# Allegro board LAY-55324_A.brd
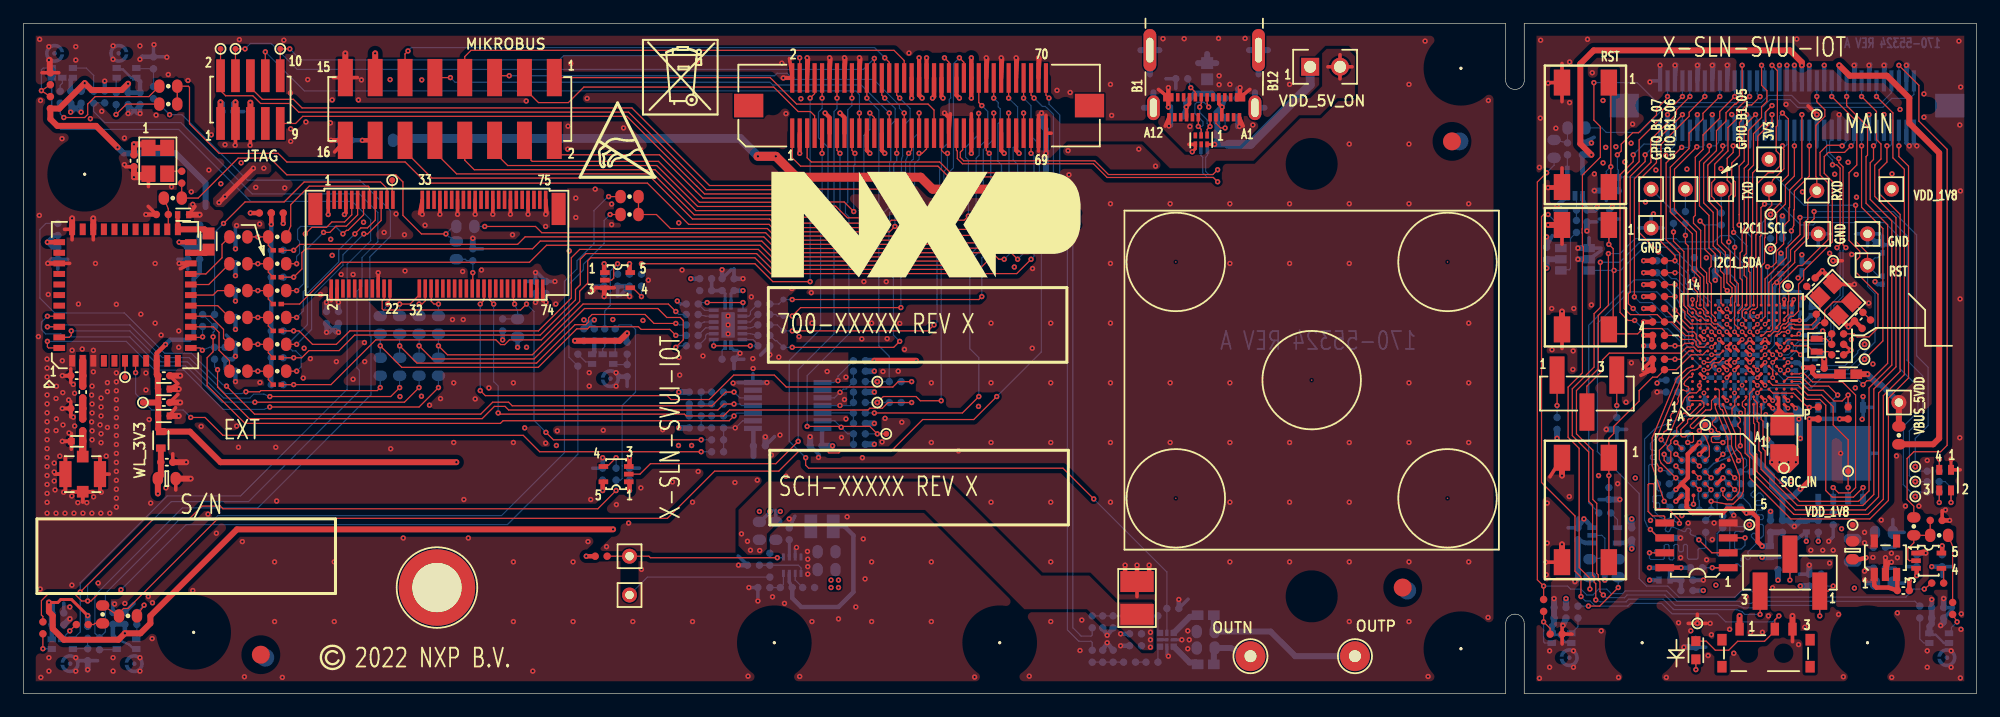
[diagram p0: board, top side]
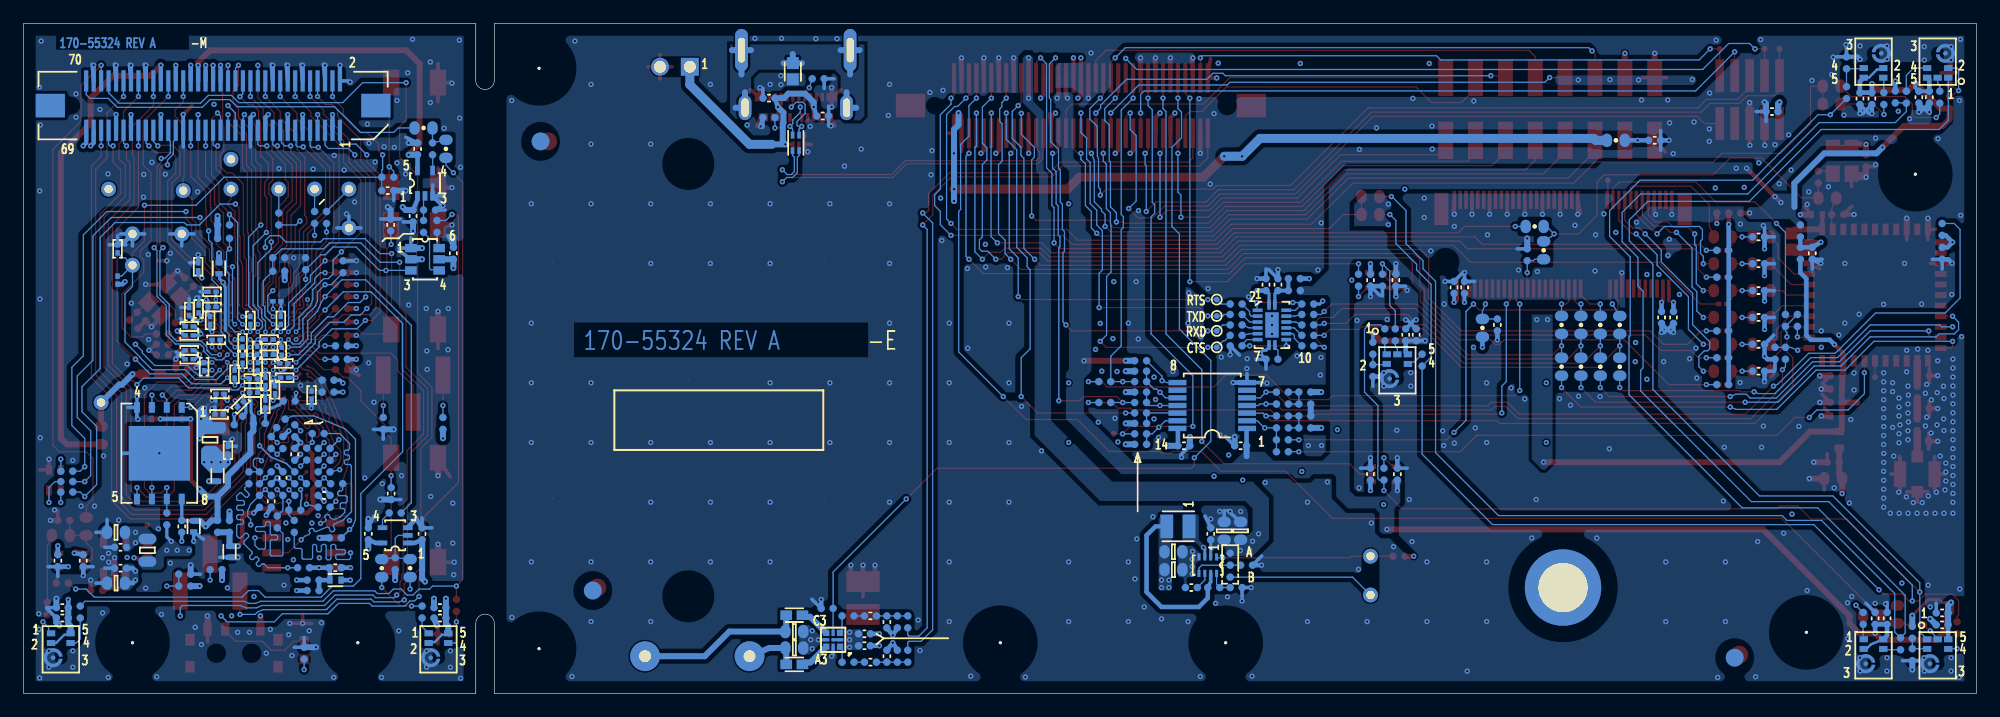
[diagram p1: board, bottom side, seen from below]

Outline 166.17 x 57.02 mm; copper layers: TOP, L2_GND, L3_PWR, BOTTOM. Coordinates in mm from the lower left corner of the outline.
Outline path: 0,57.02 0,0 126.11,0 126.11,5.97 arc(126.9,6.76) 127.69,5.97 127.69,0 166.17,0 166.17,57.02 127.69,57.02 127.69,52.32 arc(126.9,51.41) 126.11,52.32 126.11,57.02 0,57.02

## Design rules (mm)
constraint set DEFAULT: min track width 0.102
net group RF: nets N103040633 RF_50E
net group USB: nets USB_DM USB_DP
net group USB_EXT: nets USB_DM_EXT USB_DP_EXT
net group POWER: nets DCDC_3V3 DCDC_SW N102577756 N103040281 N103040289 N103040293 N103059335 USB_OTG1_VBUS VBUS_5VDD_E VDD_OPI VDD_QSPI VDD_SOC_IN VDD_USB_3V
net group PSRAM: nets PSRAM_RST_N
net group PSRAM_DATA4: nets PSRAM_DATA4

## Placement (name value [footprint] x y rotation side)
BMP60  BUMPER_315  [BUMPER_RD_315MIL]  98.04 36.73 0 top
BMP61  BUMPER_315  [BUMPER_RD_315MIL]  109.6 26.67 0 top
BMP62  BUMPER_315  [BUMPER_RD_315MIL]  98.04 16.61 0 top
BMP63  BUMPER_315  [BUMPER_RD_315MIL]  121.16 16.61 0 top
BMP64  BUMPER_315  [BUMPER_RD_315MIL]  121.16 36.73 0 top
C1  10PF  [CC0402_25]  5.04 25.65 270 top
C2  TBD  [CC0402_25]  4.53 24.26 180 top
C3  TBD  [CC0402_25]  4.53 27.05 180 top
C4  0.1UF  [CC0402_25]  135.18 42.8 180 bottom
C5  0.1UF  [CC0402_25]  102.74 50.67 0 bottom
C6  10uF  [CC0402_TOL0P2]  11.94 23.62 0 top
C7  0.1UF  [CC0402_25]  11.94 24.77 0 top
C10  0.1UF  [CC0402_25]  98.17 49.15 180 bottom
C11  0.1UF  [CC0402_25]  152.7 27.69 0 top
C16  0.1UF  [CC0402_25]  9.4 45.34 270 top
C19  4.7pF  [CC0402_25]  156.14 32.08 225 top
C20  4.7uF  [CC0402_TOL0P15]  11.94 25.91 0 top
C21  0.1UF  [CC0402_25]  11.94 27.05 0 top
C22  18PF  [CC0402_25]  154.36 28.83 0 top
C23  4.7pF  [CC0402_25]  152.08 35.01 45 top
C24  0.22UF  [CC0201]  148.77 20.7 90 bottom
C25  0.1UF  [CC0402_25]  152.7 14.22 270 bottom
C26  4.7uF  [CC0402_TOL0P15]  151.69 14.22 270 bottom
C27  1000pF  [CC0402_25]  92.71 6.1 270 bottom
C28  1000pF  [CC0402_25]  92.71 3.17 90 bottom
C29  0.022UF  [CC0402_25]  94.11 6.6 0 bottom
C30  0.022UF  [CC0402_25]  94.11 2.67 0 bottom
C31  220PF  [CC0603_OV]  100.58 5.27 180 bottom
C32  220PF  [CC0603_OV]  100.58 3.87 180 bottom
C35  0.1UF  [CC0402_25]  17.4 49.53 0 bottom
C36  0.1UF  [CC0402_25]  27.38 47.08 180 bottom
C37  0.1UF  [CC0402_25]  134.92 39.88 90 bottom
C38  0.1UF  [CC0402_25]  162.86 7.31 0 bottom
C39  0.1UF  [CC0402_25]  130.73 7.31 0 bottom
C40  200PF  [CC0402_25]  130.73 6.42 0 bottom
C41  200PF  [CC0402_25]  162.86 6.42 0 bottom
C60  2.2UF  [CC0402_25]  13.97 37.47 270 bottom
C61  33PF  [CC0402_25]  18.54 27.43 180 bottom
C62  33PF  [CC0402_25]  18.54 29.72 180 bottom
C63  33PF  [CC0402_25]  18.54 32 180 bottom
C66  33PF  [CC0402_25]  18.54 34.29 180 bottom
C67  33PF  [CC0402_25]  18.54 36.58 180 bottom
C68  33PF  [CC0402_25]  18.54 38.86 180 bottom
C69  4.7uF  [CC0201]  152.07 29.21 0 bottom
C70  4.7uF  [CC0402_TOL0P15]  13.59 40.75 0 top
C71  0.22UF  [CC0201]  152.07 28.45 0 bottom
C72  4.7uF  [CC0201]  152.07 32.51 90 bottom
C73  0.22UF  [CC0201]  151.27 32.73 90 bottom
C74  0.1uF  [CC0201]  158.17 37.85 90 bottom
C75  0.22UF  [CC0201]  152.07 30.48 0 bottom
C76  0.22UF  [CC0201]  149.78 30.1 0 bottom
C77  1UF  [CC0201]  150.8 27.81 270 bottom
C78  0.22UF  [CC0201]  150.13 32.89 0 bottom
C79  1UF  [CC0201]  150.13 34.19 0 bottom
C80  4.7uF  [CC0201]  152.07 31.24 0 bottom
C81  0.22UF  [CC0201]  150.29 31.75 90 bottom
C82  4.7uF  [CC0201]  141.66 25.4 270 bottom
C83  4.7uF  [CC0201]  145.59 24.64 90 bottom
C84  0.1uF  [CC0201]  147.53 29.83 90 bottom
C85  0.22UF  [CC0201]  144.28 31.76 90 bottom
C86  0.22UF  [CC0201]  147.7 24.61 315 bottom
C87  0.22UF  [CC0201]  149.53 23.75 0 bottom
C88  10uF  [CC0402_TOL0P2]  149.53 36.2 90 bottom
C89  0.1uF  [CC0201]  147.53 28.45 90 bottom
C90  0.22UF  [CC0201]  144.02 28.09 180 bottom
C91  33uF  [CC0805_OV]  150.29 21.59 90 bottom
C92  0.22UF  [CC0201]  145.58 26.55 270 bottom
C93  10uF  [CC0402_TOL0P2]  149.66 18.54 270 bottom
C94  0.22UF  [CC0201]  145.25 28.83 0 bottom
C95  4.7uF  [CC0201]  146.28 29.2 270 bottom
C96  0.22UF  [CC0201]  146.23 27.83 90 bottom
C97  0.22UF  [CC0201]  144.2 29.13 270 bottom
C98  0.1uF  [CC0201]  144.76 25.85 270 bottom
C99  0.1uF  [CC0201]  143.95 26.88 180 bottom
C100  4.7uF  [CC0201]  151.31 36.32 90 bottom
C101  0.22UF  [CC0201]  145.26 30.12 180 bottom
C102  0.22UF  [CC0201]  149.45 25.5 0 bottom
C106  0.1uF  [CC0201]  146.86 31.75 90 bottom
C107  4.7uF  [CC0201]  146.58 25.6 180 bottom
C108  0.1uF  [CC0201]  146.61 26.8 180 bottom
C112  4.7uF  [CC0201]  148.21 27.18 90 bottom
C114  0.1UF  [CC0402_25]  94.61 4.06 180 bottom
C116  1.0UF  [CC0402_25]  94.61 5.08 180 bottom
C122  100UF  [CC1210]  94.74 8.13 90 top
C123  0.1UF  [CC0402_25]  134.89 17.02 270 bottom
C218  0.1UF  [CC0402_25]  159.94 8.76 0 top
C221  22uF  [CC0603_OV]  155.63 12.19 270 top
C222  22uF  [CC0603_OV]  158.29 13.72 0 bottom
C223  0.1UF  [CC0402_25]  157.91 12.45 0 bottom
C225  0.1UF  [CC0402_25]  157.91 10.67 0 bottom
C226  22uF  [CC0603_OV]  158.29 9.4 0 bottom
C227  0.1UF  [CC0402_25]  40.77 31.37 270 bottom
C228  0.1UF  [CC0402_25]  44.45 34.56 90 bottom
C229  0.1UF  [CC0402_25]  43.56 34.56 90 bottom
C230  0.1UF  [CC0402_25]  25.78 32 270 bottom
C231  0.1UF  [CC0402_25]  26.8 32 270 bottom
C232  0.1UF  [CC0402_25]  132.64 46.36 90 bottom
C233  0.1UF  [CC0402_25]  133.02 40.64 270 bottom
C236  0.1UF  [CC0402_25]  163.25 11.3 270 bottom
C237  0.1UF  [CC0402_25]  161.09 11.3 270 bottom
C238  0.1UF  [CC0402_25]  136.83 13.59 90 bottom
C239  0.1UF  [CC0402_25]  132.26 13.59 90 bottom
C240  200PF  [CC0402_25]  9.92 50.63 270 bottom
C241  0.1UF  [CC0402_25]  8.9 50.63 270 bottom
C242  200PF  [CC0402_25]  7.61 6.39 90 bottom
C243  0.1UF  [CC0402_25]  8.63 6.39 90 bottom
C244  200PF  [CC0402_25]  48.56 30.53 90 bottom
C245  0.1UF  [CC0402_25]  47.68 30.53 90 bottom
C246  200PF  [CC0402_25]  4.01 50.75 270 bottom
C247  0.1UF  [CC0402_25]  4.9 50.75 270 bottom
C248  200PF  [CC0402_25]  2.92 5.84 0 bottom
C249  0.1UF  [CC0402_25]  2.92 6.86 0 bottom
C250  0.1UF  [CC0402_25]  51.56 35.18 270 bottom
C251  0.1UF  [CC0402_25]  49.4 35.18 270 bottom
C252  0.1UF  [CC0402_25]  51.56 18.67 90 bottom
C253  0.1UF  [CC0402_25]  49.28 18.67 90 bottom
C254  0.1UF  [CC0402_25]  129.59 37.47 90 bottom
C255  1.0UF  [CC0402_25]  140.59 16.86 0 bottom
C256  4.7uF  [CC0402_TOL0P15]  148.64 12.06 270 bottom
C257  0.1UF  [CC0402_25]  144.09 18.36 90 bottom
C258  0.1UF  [CC0402_25]  143.09 20.36 270 bottom
C259  4.7uF  [CC0402_TOL0P15]  139.62 9.65 180 bottom
C260  1.0UF  [CC0402_25]  139.64 10.71 180 bottom
C261  0.1UF  [CC0402_25]  60.45 34.8 90 bottom
C262  0.1UF  [CC0402_25]  59.44 34.8 90 bottom
C269  0.1UF  [CC0402_25]  67.44 21.08 180 bottom
C270  0.1UF  [CC0402_25]  62.61 21.08 0 bottom
C271  10uF  [CC0603_OV]  62.61 13.84 90 bottom
C272  10uF  [CC0603_OV]  64.01 13.84 90 bottom
C273  0.1UF  [CC0402_25]  65.15 13.59 90 bottom
C274  10uF  [CC0603_OV]  68.33 12.06 180 bottom
C275  10uF  [CC0603_OV]  68.33 10.54 180 bottom
C276  0.01UF  [CC0402_25]  66.8 9.02 0 bottom
C277  0.1UF  [CC0402_25]  145.09 16.36 270 bottom
C278  22uF  [CC0603_OV]  12.19 18.29 0 top
C279  0.1UF  [CC0402_25]  12.19 19.68 0 top
CON60  USB_TYPE_C  [CON24_USB_TYPEC_RA_9P64X8P55_SMT]  100.46 53.21 180 top
D1  PGB2010402KRHF  [DIODE_0402]  4.55 21.46 0 top
D2  LED\RED  [LED_0603]  142.29 3.68 270 top
D60  APTF1616LSEKJ3ZGKQBC  [LED4_1P75_1P8SQ_SMT]  163.5 18.16 270 top
FB1  28Ohm  [IND_0603A]  100.71 52.96 90 bottom
FB2  1K  [IND_0603]  155.24 27.18 180 top
FB3  120 OHM@100MHz  [IND_0603]  100.58 6.67 0 bottom
FB4  120 OHM@100MHz  [IND_0603]  100.58 2.48 0 bottom
J1  CONN COAX RF  [CON4_COAX_RF_2P7SQ_SMT]  5.04 18.67 180 top
J2  PLUG 2X35  [CON70M_25_SM]  150.04 50.04 0 bottom
J3  CON 2X35  [CON70_SKT_0P635_SM]  76.2 50.04 0 top
J8  M.2 MINI CARD  [CON_67_0P5_22X7P75_RA]  35.18 38.12 0 top
J60  HDR 1X2  [HDR102]  109.47 53.34 90 top
J61  HDR_1X3  [HDR103_STAG_SM]  150.29 10.29 90 top
J62  FTSH-105-01-F-DV-K  [HDR205_10M_50_SM_K]  19.3 50.55 0 top
J63  HDR_1X3  [HDR103_STAG_SM]  133.02 25.53 270 top
J64  HDR_2X8  [HDR208_TSM_SM]  36.27 49.75 270 top
L1  600 OHM  [IND_1608]  11.68 21.59 90 top
L3  4.7uH  [IND_2P7X2P2MM]  149.66 21.59 270 top
L4  1uH  [IND_2P7X2P2MM]  67.94 14.22 0 bottom
L60  90Ohms@100MHz  [IND4_CHOKE_0603]  100.46 46.86 270 bottom
L61  2.2uH  [IND_0603A]  15.75 38.46 270 top
LS1  ASE02808MR-LW150-R  [SPEAKER_31X28_TH]  109.6 8.27 180 top
M1  SPH0690LM4H-1  [MIC5_3P6X2P75MM]  162.99 3.76 180 bottom
M2  SPH0690LM4H-1  [MIC5_3P6X2P75MM]  130.86 3.76 180 bottom
M3  SPH0690LM4H-1  [MIC5_3P6X2P75MM]  8.76 53.77 0 bottom
M4  SPH0690LM4H-1  [MIC5_3P6X2P75MM]  8.76 3.25 180 bottom
NOREF  -  []  95.84 54.76 0 top
NOREF#2  -  []  63.5 14.35 0 top
NOREF#3  -  []  157.66 16.4 0 top
NOREF#4  -  []  96.96 56.04 90 top
NOREF#5  -  []  91.4 46.74 90 top
NOREF#6  -  []  111.79 8.47 0 top
NOREF#7  -  []  61.7 50.04 0 top
NOREF#8  -  []  151.36 13.65 0 top
NOREF#9  -  []  47.37 43.94 0 top
NOREF#10  -  []  2.4 53.23 0 top
NOREF#11  -  []  1.14 8.51 0 top
NOREF#12  -  [unnamed#2]  121.54 46.99 0 top
NOREF#13  -  []  1.93 55.57 0 top
NOREF#14  -  []  162.6 17.26 0 top
NOREF#15  -  []  -321.69 -386.08 0 top
NOREF#16  -  []  99.96 49.04 0 top
NOREF#17  -  []  144.86 2.08 0 top
NOREF#18  -  []  96.51 3.8 0 top
NOREF#19  -  []  14.69 27.86 90 top
NOREF#20  -  []  13.11 40.75 0 top
NOREF#21  -  []  150.45 24.6 90 top
NOREF#22  -  []  24.83 41.24 90 top
NOREF#23  -  []  131.16 19.19 90 top
NOREF#24  -  []  146.76 3.43 0 top
NOREF#25  -  []  10.21 25.58 0 top
NOREF#26  -  []  97.28 5.16 0 top
NOREF#27  -  []  96.14 49.85 0 top
NOREF#28  -  []  61.24 29.57 90 top
NOREF#29  -  []  50.65 25.71 0 top
NOREF#30  -  []  66.16 10.22 90 top
NOREF#31  -  []  3.3 2.54 90 top
NOREF#32  -  []  24.18 42.14 0 top
NOREF#33  -  []  11.46 25.91 0 top
NOREF#34  -  [unnamed#2]  122.3 3.81 0 top
NOREF#35  -  []  163 17.29 0 top
NOREF#36  -  []  131.16 19.19 0 top
NOREF#37  -  []  9.59 52.41 90 top
NOREF#38  -  []  167.12 1.96 90 top
NOREF#39  -  []  141.23 33.75 0 top
NOREF#40  -  []  152.02 28.79 0 top
NOREF#41  -  []  141.23 33.83 0 top
NOREF#42  -  []  69.3 15.32 0 top
NOREF#43  -  [unnamed#2]  63.88 4.32 0 top
NOREF#44  -  []  127.69 57.02 0 top
NOREF#45  -  []  149.01 5.48 0 top
NOREF#46  -  [unnamed#3]  126.11 6.35 0 top
NOREF#47  -  []  139.05 9.33 0 top
NOREF#48  -  []  130.03 4.3 0 top
NOREF#49  -  [unnamed#2]  20.19 3.3 0 top
NOREF#50  -  []  2.4 3.79 0 top
NOREF#51  -  []  4.2 52.41 90 top
NOREF#52  -  []  52.7 49.28 0 top
NOREF#53  -  []  59.69 29.65 0 top
NOREF#54  -  []  48.38 28.05 0 top
NOREF#55  -  []  136.19 50.04 0 top
NOREF#56  -  []  97.87 4.57 90 top
NOREF#57  -  []  149.66 18.07 90 top
NOREF#58  -  []  4.09 17.56 0 top
NOREF#59  -  []  5.53 17.67 90 top
NOREF#60  -  []  109.6 8.27 90 top
NOREF#61  -  []  2.59 39.96 0 top
NOREF#62  -  []  151.69 13.75 90 top
NOREF#63  -  []  7.93 53.23 0 top
NOREF#64  -  []  162.16 4.3 90 top
NOREF#65  -  []  98.28 48.66 0 top
NOREF#66  -  []  13.14 28.31 90 top
NOREF#67  -  []  98.28 47.71 90 top
NOREF#68  -  []  148.97 11.49 90 top
NOREF#69  -  []  126.11 57.02 0 top
NOREF#70  -  []  2.4 3.79 90 top
NOREF#71  -  []  97.87 3.99 90 top
NOREF#72  -  []  69.3 13.12 90 top
NOREF#73  -  []  3.04 38.41 0 top
NOREF#74  -  []  26.18 34.47 0 top
NOREF#75  -  []  38.25 10.09 0 top
NOREF#76  -  []  97.46 49.04 0 top
NOREF#77  -  []  4.14 39.5 0 top
NOREF#78  -  []  162.99 3.05 90 top
NOREF#79  -  []  53.4 25.71 90 top
NOREF#80  -  []  58.72 30.12 90 top
NOREF#81  -  []  152.02 28.79 90 top
NOREF#82  -  []  149.31 17.94 0 top
NOREF#83  -  []  4.68 1.45 0 top
NOREF#84  -  []  8.76 2.54 90 top
NOREF#85  -  []  25.18 36.74 90 top
NOREF#86  -  []  25.18 36.74 0 top
NOREF#87  -  []  49.28 26.8 90 top
NOREF#88  -  []  63.75 50.04 0 top
NOREF#89  -  []  126.11 10.56 0 top
NOREF#90  -  []  7.43 1.45 90 top
NOREF#91  -  []  31.75 -36.83 0 top
NOREF#92  -  []  65.65 10.22 0 top
NOREF#93  -  [unnamed#2]  5.21 44.2 0 top
NOREF#94  -  []  162.16 4.3 0 top
NOREF#95  -  []  65.41 47.69 0 top
NOREF#96  -  []  144.51 2.28 90 top
NOREF#97  -  []  7.93 3.79 90 top
NOREF#98  -  []  14.23 29.41 90 top
NOREF#99  -  [unnamed#2]  137.72 4.32 270 top
NOREF#100  -  []  63.37 28.19 0 top
NOREF#101  -  []  139.05 9.33 90 top
NOREF#102  -  []  100.74 46.2 90 top
NOREF#103  -  []  48.38 28.05 90 top
NOREF#104  -  []  96.14 49.85 90 top
NOREF#105  -  []  26.29 3.05 0 top
NOREF#106  -  []  149.18 35.6 90 top
NOREF#107  -  [unnamed#3]  126.11 27.18 0 top
NOREF#108  -  []  150.04 52.14 0 top
NOREF#109  -  []  96.14 49.85 90 top
NOREF#110  -  []  10.14 1.45 0 top
NOREF#111  -  []  95.64 48.74 90 top
NOREF#112  -  []  58.72 32.12 90 top
NOREF#113  -  []  152.01 13.65 90 top
NOREF#114  -  []  155.37 7.81 90 top
NOREF#115  -  []  7.93 3.79 0 top
NOREF#116  -  []  125.35 -16.08 0 top
NOREF#117  -  []  -297.05 135.51 0 top
NOREF#118  -  []  13.01 40.42 0 top
NOREF#119  -  []  148.56 20.24 90 top
NOREF#120  -  []  150.01 17.94 90 top
NOREF#121  -  []  150.45 24.6 90 top
NOREF#122  -  []  14.16 40.42 90 top
NOREF#123  -  []  148.32 11.49 0 top
NOREF#124  -  []  148.64 11.59 90 top
NOREF#125  -  []  149.18 36.79 0 top
NOREF#126  -  []  3.69 22.72 0 top
NOREF#127  -  []  63.63 35.43 0 top
NOREF#128  -  []  61 47.37 0 top
NOREF#129  -  []  130.86 3.05 90 top
NOREF#130  -  []  139.15 9.65 0 top
NOREF#131  -  []  14.48 5.21 0 top
NOREF#132  -  []  132.24 1.96 0 top
NOREF#133  -  []  63 11.57 90 top
NOREF#134  -  []  163 17.29 90 top
NOREF#135  -  []  137.99 50.04 0 top
NOREF#136  -  []  151.23 23.83 90 top
NOREF#137  -  []  9.59 53.23 90 top
NOREF#138  -  []  95.64 57.29 0 top
NOREF#139  -  []  146.01 5.48 0 top
NOREF#140  -  []  10.21 25.58 90 top
NOREF#141  -  []  139.24 52.14 0 top
NOREF#142  -  [unnamed#2]  14.48 5.21 0 top
NOREF#143  -  []  32.23 42.14 90 top
NOREF#144  -  []  24.83 41.24 0 top
NOREF#145  -  []  130.03 4.3 90 top
NOREF#146  -  []  96.14 49.85 90 top
NOREF#147  -  []  7.39 55.57 0 top
NOREF#148  -  []  134.99 1.96 90 top
NOREF#149  -  []  144.86 2.08 90 top
NOREF#150  -  []  6.39 20.02 90 top
NOREF#151  -  [unnamed#2]  156.9 4.32 270 top
NOREF#152  -  [unnamed#2]  83.06 4.32 0 top
NOREF#153  -  []  12.89 1.45 90 top
NOREF#154  -  []  4.14 39.5 0 top
NOREF#155  -  []  149.53 35.72 90 top
NOREF#156  -  []  148.56 20.24 0 top
NOREF#157  -  [unnamed#2]  122.3 53.21 0 top
NOREF#158  -  []  67 14.22 0 top
NOREF#159  -  []  11.46 23.62 0 top
NOREF#160  -  []  166.17 0 90 top
NOREF#161  -  []  96.51 3.8 90 top
NOREF#162  -  []  96.7 5.16 0 top
NOREF#163  -  []  26.18 34.47 0 top
NOREF#164  -  []  157.66 16.4 90 top
NOREF#165  -  []  4.68 55.57 90 top
NOREF#166  -  []  164.37 1.96 0 top
NOREF#167  -  [unnamed#2]  117.35 9.02 0 top
NOREF#168  -  []  152.57 29.09 90 top
NOREF#169  -  []  26.18 34.47 0 top
NOREF#170  -  []  0 57.02 0 top
NOREF#171  -  [unnamed#4]  35.18 9.02 90 top
NOREF#172  -  []  58.72 30.12 0 top
NOREF#173  -  []  11.34 24.47 0 top
NOREF#174  -  []  100.21 50.74 0 top
NOREF#175  -  []  97.41 50.74 0 top
NOREF#176  -  []  63 13.77 0 top
NOREF#177  -  []  10.14 55.57 90 top
NOREF#178  -  []  160.83 47.94 90 top
NOREF#179  -  []  26.18 34.47 90 top
NOREF#180  -  []  156.85 -16.08 90 top
NOREF#181  -  []  57.64 32.17 0 top
NOREF#182  -  []  4.2 53.23 90 top
NOREF#183  -  []  149.66 20.64 90 top
NOREF#184  -  []  162.6 17.26 90 top
NOREF#185  -  []  14.23 29.41 90 top
NOREF#186  -  [unnamed#3]  126.11 48.01 0 top
NOREF#187  -  []  100.18 46.2 0 top
NOREF#188  -  []  11.34 23.27 90 top
NOREF#189  -  []  115.9 20.73 180 bottom
NOREF#190  -  [unnamed#2]  20.57 3.05 180 bottom
NOREF#191  -  [unnamed#2]  122.17 46.99 180 bottom
NOREF#192  -  [unnamed#2]  117.73 8.76 180 bottom
R1  1K  [RC0402_25]  135.18 43.94 180 bottom
R2  0  [RC0402_25]  5.04 22.86 90 top
R3  5.1K  [RC0402_25]  98.55 52.32 180 bottom
R5  5.1K  [RC0402_25]  102.74 49.02 0 bottom
R6  0  [RC0603_OV]  159.56 21.97 270 top
R8  2.2M  [RC0402_25]  156.79 31.43 225 top
R10  22  [RC0402_25]  13.46 43.94 270 top
R11  220K  [RC0402_25]  154.36 29.72 0 top
R12  499K  [RC0402_25]  154.36 30.61 180 top
R13  1.0M  [RC0402_25]  152.89 31.92 135 top
R14  10K  [RC0402_25]  155.24 23.88 90 top
R15  4.7K  [RC0402_25]  149.15 38.73 180 bottom
R16  4.7K  [RC0402_25]  149.15 39.88 180 bottom
R17  10K  [RC0402_25]  152.7 23.88 90 top
R18  100K  [RC0402_25]  139.12 36.83 0 top
R19  0  [RC0201]  21.59 37.72 0 top
R20  0  [RC0201]  21.59 33.15 180 top
R21  100K  [RC0402_25]  144.45 37.08 0 bottom
R22  1K  [RC0402_25]  144.45 35.94 0 bottom
R23  1K  [RC0402_25]  152.45 9.14 0 bottom
R24  100K  [RC0402_25]  152.45 10.16 0 bottom
R25  0  [RC0201]  21.59 35.43 0 top
R26  0  [RC0201]  21.59 28.57 0 top
R27  0  [RC0201]  21.59 26.29 0 top
R29  0  [RC0201]  21.59 30.86 0 top
R30  10K  [RC0402_25]  153.97 14.86 90 bottom
R31  100K  [RC0402_25]  139.12 35.81 0 top
R32  1K  [RC0402_25]  139.12 28.45 0 bottom
R33  100K  [RC0201]  144.6 33.38 180 bottom
R34  100K  [RC0402_25]  139.12 31.62 0 top
R35  100K  [RC0402_25]  139.12 28.45 0 top
R36  100K  [RC0402_25]  139.12 32.77 0 top
R37  100K  [RC0402_25]  139.12 27.56 0 top
R38  100K  [RC0402_25]  139.12 29.59 0 top
R39  100K  [RC0402_25]  139.12 33.78 0 top
R40  1K  [RC0402_25]  139.12 29.59 0 bottom
R41  1K  [RC0402_25]  139.12 34.8 0 top
R42  100K  [RC0402_25]  139.12 30.48 0 top
R43  10K  [RC0402_25]  90.93 6.1 270 bottom
R44  10K  [RC0402_25]  90.93 3.17 90 bottom
R45  10K  [RC0402_25]  91.82 6.1 270 bottom
R46  10K  [RC0402_25]  91.82 3.17 90 bottom
R47  82K  [RC0402_25]  96.01 6.6 180 bottom
R48  82K  [RC0402_25]  96.01 2.67 180 bottom
R49  0  [RC0603_OV]  130.23 46.36 90 bottom
R53  33  [RC0402_25]  164.13 7.24 90 top
R54  33  [RC0402_25]  132.26 6.93 90 bottom
R62  1K  [RC0402_25]  149.78 10.54 180 bottom
R65  100K  [RC0402_25]  135.56 22.99 90 bottom
R69  10.0K  [RC0201]  158.17 35.18 90 bottom
R70  1K  [RC0402_25]  130.48 22.99 90 bottom
R71  30K  [RC0402_25]  147.88 23.24 135 bottom
R72  10K  [RC0402_25]  21.59 37.72 0 bottom
R73  10K  [RC0402_25]  21.59 35.43 0 bottom
R74  10K  [RC0402_25]  21.59 28.57 0 bottom
R75  10K  [RC0402_25]  21.59 26.29 0 bottom
R76  10K  [RC0402_25]  21.59 30.86 0 bottom
R77  100K  [RC0402_25]  142.16 36.58 270 bottom
R78  100K  [RC0402_25]  138.99 36.32 270 bottom
R79  10K  [RC0402_25]  97.79 7.24 0 bottom
R80  750  [RC0402_25]  162.48 18.03 0 bottom
R81  82  [RC0402_25]  162.48 18.92 0 bottom
R82  470  [RC0402_25]  162.48 17.14 0 bottom
R213  0  [RC0805_OV]  155.63 12.19 270 bottom
R214  0  [RC0402_25]  140.26 25.65 180 bottom
R215  0  [RC0402_25]  140.26 26.67 0 bottom
R216  0  [RC0402_25]  143.56 24.89 0 bottom
R217  0  [RC0402_25]  146.1 22.99 0 bottom
R218  0  [RC0603_OV]  42.04 31.12 90 bottom
R219  33  [RC0402_25]  131.37 46.36 270 bottom
R221  0  [RC0402_25]  129.34 7.49 90 top
R222  0  [RC0603_OV]  51.56 42.29 180 top
R223  0  [RC0603_OV]  132.13 48.13 180 bottom
R224  33  [RC0402_25]  162.86 9.4 180 top
R225  0  [RC0603_OV]  160.83 14.22 270 top
R226  0  [RC0603_OV]  162.99 13.46 180 top
R227  33  [RC0402_25]  134.54 15.37 180 bottom
R228  0  [RC0603_OV]  8.89 6.6 180 top
R229  0  [RC0603_OV]  133.27 10.67 90 bottom
R230  33  [RC0402_25]  7.88 50.63 270 bottom
R231  33  [RC0402_25]  9.64 6.39 90 bottom
R232  33  [RC0402_25]  49.45 30.53 90 bottom
R233  33  [RC0402_25]  5 5.87 0 top
R234  33  [RC0402_25]  3.12 50.75 270 bottom
R235  33  [RC0402_25]  52.58 35.18 90 bottom
R236  100K  [RC0402_25]  50.55 35.18 270 bottom
R237  10K  [RC0402_25]  51.36 29.39 270 bottom
R238  100K  [RC0402_25]  51.36 27.48 270 bottom
R239  10K  [RC0402_25]  2.29 50.29 90 top
R240  100K  [RC0402_25]  2.29 52.32 90 top
R241  10K  [RC0402_25]  5.46 5.21 270 bottom
R242  100K  [RC0402_25]  5.46 3.3 270 bottom
R243  0  [RC0603_OV]  12.32 51.69 0 top
R244  0  [RC0603_OV]  135.69 10.67 270 bottom
R245  0  [RC0402_25]  11.06 51.14 270 bottom
R247  100K  [RC0402_25]  11.06 53.68 90 bottom
R249  100K  [RC0402_25]  130.4 5.05 0 top
R252  100K  [RC0402_25]  6.91 50.77 90 bottom
R254  0  [RC0402_25]  6.47 4.23 90 bottom
R255  33  [RC0402_25]  5.97 50.75 90 bottom
R256  33  [RC0402_25]  50.42 18.67 90 bottom
R257  33  [RC0402_25]  50.34 30.53 270 bottom
R259  100K  [RC0402_25]  162.74 14.73 0 top
R260  33  [RC0402_25]  132.13 39.75 270 bottom
R261  100K  [RC0402_25]  131.62 41.15 180 bottom
R262  220  [RC0402_25]  130.99 39.75 270 bottom
R263  499  [RC0402_25]  142.29 3.43 90 bottom
R264  0  [RC0402_25]  139.52 17.86 180 bottom
R265  0  [RC0402_25]  141.59 17.86 0 bottom
R266  0  [RC0402_25]  142.07 20.38 270 bottom
R267  0  [RC0402_25]  143.59 16.86 180 bottom
R268  0  [RC0402_25]  143.09 15.61 180 bottom
R269  0  [RC0402_25]  140.59 15.86 0 bottom
R270  0  [RC0402_25]  140.59 18.86 0 bottom
R271  0  [RC0402_25]  140.59 19.86 0 bottom
R272  0  [RC0402_25]  140.59 20.86 0 bottom
R273  0  [RC0402_25]  141.1 22.12 180 bottom
R274  0  [RC0402_25]  144.58 14.61 270 bottom
R275  0  [RC0402_25]  143.13 14.22 270 bottom
R276  0  [RC0402_25]  146.99 18.36 90 bottom
R277  0  [RC0402_25]  144.27 22.99 315 bottom
R278  0  [RC0402_25]  146.09 18.36 270 bottom
R279  0  [RC0402_25]  145.09 21.36 270 bottom
R280  10K  [RC0402_25]  143.08 22.36 90 bottom
R281  0  [RC0402_25]  143.09 18.36 270 bottom
R282  10K  [RC0402_25]  145.09 18.36 90 bottom
R283  10K  [RC0402_25]  142.34 10.71 0 bottom
R284  100K  [RC0402_25]  139.64 13.25 0 bottom
R285  100K  [RC0402_25]  144.1 21.36 90 bottom
R286  0  [RC0402_25]  148.64 14.22 270 bottom
R287  0  [RC0402_25]  149.66 14.22 90 bottom
R288  10K  [RC0402_25]  146.09 16.36 90 bottom
R289  33  [RC0402_25]  56.9 32.26 0 bottom
R290  33  [RC0402_25]  56.9 31.37 0 bottom
R291  33  [RC0402_25]  62.99 31.37 0 bottom
R292  33  [RC0402_25]  62.99 30.48 0 bottom
R293  0  [RC0603_OV]  37.59 39.75 180 bottom
R294  100K  [RC0402_25]  71.12 28.32 180 bottom
R295  10K  [RC0402_25]  59.05 22.61 0 bottom
R296  10K  [RC0402_25]  59.05 23.62 0 bottom
R297  10K  [RC0402_25]  71.12 21.21 180 bottom
R298  10K  [RC0402_25]  71.12 22.99 180 bottom
R300  0  [RC0402_25]  59.05 21.59 0 bottom
R301  0  [RC0402_25]  71.12 22.1 180 bottom
R302  0  [RC0402_25]  21.59 40.89 180 top
R303  0  [RC0402_25]  20.57 40.89 180 top
R304  0  [RC0402_25]  16.26 31.75 270 bottom
R306  0  [RC0402_25]  71.12 23.88 180 bottom
R307  10K  [RC0402_25]  71.12 25.65 180 bottom
R308  10K  [RC0402_25]  59.05 24.64 0 bottom
R309  0  [RC0402_25]  71.12 24.77 180 bottom
R310  10K  [RC0402_25]  59.05 25.65 0 bottom
R311  10K  [RC0402_25]  71.12 27.43 180 bottom
R312  200K  [RC0402_25]  64.9 9.02 0 bottom
R313  10K  [RC0402_X2]  63.5 11.43 270 bottom
R314  100K  [RC0402_25]  49.15 11.68 0 top
R315  44.2K  [RC0402_25]  62.99 9.02 180 bottom
R316  0  [RC0603_OV]  36.83 37.72 270 bottom
R317  100K  [RC0402_25]  62.1 10.92 180 bottom
R318  0  [RC0402_25]  74.17 24.77 0 bottom
R319  0  [RC0402_25]  74.17 26.54 0 bottom
R321  0  [RC0402_25]  14.99 39.37 90 bottom
R322  0  [RC0603_OV]  12.7 42.16 0 top
R323  220K  [RC0402_25]  11.81 40.77 180 top
R324  0  [RC0603_OV]  18.29 36.58 180 top
R325  0  [RC0603_OV]  18.29 38.86 180 top
R326  0  [RC0603_OV]  18.29 27.43 180 top
R327  0  [RC0603_OV]  18.29 29.72 180 top
R328  0  [RC0603_OV]  18.29 32 180 top
R329  0  [RC0603_OV]  18.29 34.29 180 top
R330  0  [RC0603_OV]  21.59 34.29 180 top
R331  0  [RC0603_OV]  21.59 32 180 top
R332  0  [RC0603_OV]  21.59 36.58 180 top
R333  0  [RC0603_OV]  21.59 38.86 180 top
R334  0  [RC0603_OV]  21.59 27.43 180 top
R335  0  [RC0603_OV]  21.59 29.72 180 top
R336  0  [RC0402_25]  15.24 31.75 270 bottom
R337  100K  [RC0402_25]  2.92 37.47 270 bottom
R338  0  [RC0402_25]  2.92 39.5 270 bottom
R339  0  [RC0402_25]  71.12 26.54 180 bottom
R340  100K  [RC0402_25]  17.14 28.96 270 bottom
R341  0  [RC0402_25]  16.26 28.96 90 bottom
R342  0  [RC0603_OV]  35.31 27.81 90 bottom
R343  0  [RC0603_OV]  32 27.81 90 bottom
R344  0  [RC0603_OV]  30.35 27.81 90 bottom
R345  0  [RC0603_OV]  33.66 27.81 90 bottom
R346  0  [RC0603_OV]  30.35 31.37 270 bottom
R347  0  [RC0603_OV]  32 31.37 270 bottom
R348  0  [RC0603_OV]  33.66 31.37 270 bottom
R349  0  [RC0603_OV]  35.31 31.37 270 bottom
R352  0  [RC0402_25]  59.05 20.57 0 bottom
R357  0  [RC0402_25]  14.99 37.47 90 bottom
R361  100K  [RC0402_25]  38.23 37.34 90 bottom
R362  0  [RC0402_25]  161.34 6.93 90 bottom
R363  0  [RC0402_25]  1.65 5.59 90 top
R364  0  [RC0402_25]  47.17 28.37 270 bottom
R365  0  [RC0603_OV]  51.56 40.77 0 top
R366  100K  [RC0402_25]  134.54 11.05 270 bottom
R367  0  [RC0603_OV]  6.73 6.73 90 top
R368  0  [RC0603_OV]  12.32 50.16 0 top
R369  0  [RC0402_25]  56.9 30.48 0 bottom
R370  0  [RC0402_25]  56.9 29.59 0 bottom
R371  0  [RC0402_25]  62.99 33.15 0 bottom
R372  0  [RC0402_25]  62.99 32.26 0 bottom
R373  0  [RC0402_25]  59.94 28.45 0 bottom
R374  0  [RC0402_25]  56.9 33.15 180 bottom
R375  0  [RC0402_25]  62.99 29.59 0 bottom
R376  0  [RC0402_25]  58.04 35.31 0 bottom
R377  0  [RC0402_25]  58.04 34.29 180 bottom
R378  0  [RC0402_25]  57.15 22.61 0 bottom
R379  0  [RC0402_25]  57.15 23.62 180 bottom
R380  0  [RC0402_25]  57.15 25.65 0 bottom
R381  0  [RC0402_25]  57.15 24.64 180 bottom
R382  0  [RC0402_25]  141.53 8.76 180 bottom
R383  0  [RC0402_25]  141.53 9.65 0 bottom
R384  0  [RC0402_25]  144.45 40.39 90 bottom
R385  0  [RC0402_25]  141.4 40.51 90 bottom
R386  0  [RC0402_25]  140.39 40.51 90 bottom
R387  0  [RC0603_OV]  30.68 47.08 0 bottom
SW60  DTSMW-69N-V-T/R  [6_22X6_38_SW]  132.89 47.55 270 top
SW61  DTSMW-69N-V-T/R  [6_22X6_38_SW]  132.89 35.43 270 top
SW62  DTSMW-69N-V-T/R  [6_22X6_38_SW]  132.89 15.62 270 top
SW64  SW SPDT  [SW3_SPDT_SM]  148.26 3.43 180 top
TP1  -  [TPAD_020]  21.84 54.86 90 top
TP2  -  [TPAD_020]  8.64 26.92 180 top
TP3  -  [TPAD_020]  73.41 22.1 180 top
TP4  -  [TPAD_020]  72.64 24.77 180 top
TP5  -  [TPAD_020]  10.16 24.77 270 top
TP6  -  [TPAD_020]  64.64 33.53 180 bottom
TP7  -  [TPAD_020]  64.64 32.13 180 bottom
TP8  -  [TPAD_020]  64.64 30.86 180 bottom
TP9  -  [TPAD_020]  64.64 29.46 180 bottom
TP10  -  [TPAD_020]  72.64 26.54 180 top
TP11  -  [TPAD_020]  156.64 29.72 270 top
TP12  -  [TPAD_020]  156.64 28.45 270 top
TP14  -  [TPAD_020]  150.13 34.68 270 top
TP15  -  [TPAD_020]  152.58 49.28 270 top
TP16  -  [TPAD_020]  160.96 18.03 180 top
TP17  -  [TPAD_020]  148.64 37.85 270 top
TP18  -  [TPAD_020]  160.96 19.3 180 top
TP19  -  [TPAD_020]  160.96 16.76 180 top
TP20  -  [TPAD_020]  148.64 40.77 270 top
TP21  -  [TPAD_020]  149.78 19.18 270 top
TP22  -  [TPAD_020]  16.76 54.86 90 top
TP60  -  [TPAD_020]  18.03 54.86 90 top
TP61  TP  [TP_040_100MIL_TH]  104.39 3.17 270 top
TP63  TP  [TP_040_100MIL_TH]  113.28 3.17 270 top
TP64  -  [TPAD_020]  142.42 5.97 270 top
TP65  -  [TPAD_020]  153.97 36.83 270 top
TP66  -  [TPAD_020]  155.24 18.92 90 top
TP201  -  [TPAD_020]  155.63 14.35 90 top
TP202  -  [TPAD_020]  143.09 22.86 270 top
TP203  -  [TPAD_020]  31.37 43.69 270 top
TP206  -  [TPAD_020]  146.84 14.36 270 top
TP208  Test point 28mil  [TESTPOINT_050_028MIL]  51.56 8.38 180 top
TP209  Test point 28mil  [TESTPOINT_050_028MIL]  51.56 11.68 180 top
TP210  Test point 28mil  [TESTPOINT_050_028MIL]  152.7 39.12 270 top
TP211  Test point 28mil  [TESTPOINT_050_028MIL]  148.51 42.93 270 top
TP212  Test point 28mil  [TESTPOINT_050_028MIL]  152.58 42.8 270 top
TP213  Test point 28mil  [TESTPOINT_050_028MIL]  156.9 39.12 270 top
TP214  Test point 28mil  [TESTPOINT_050_028MIL]  156.9 36.45 270 top
TP215  Test point 28mil  [TESTPOINT_050_028MIL]  148.51 45.47 270 top
TP216  Test point 28mil  [TESTPOINT_050_028MIL]  144.45 42.93 0 top
TP217  Test point 28mil  [TESTPOINT_050_028MIL]  141.4 42.93 0 top
TP218  Test point 28mil  [TESTPOINT_050_028MIL]  138.48 42.93 0 top
TP220  Test point 28mil  [TESTPOINT_050_028MIL]  159.56 24.77 270 top
TP221  Test point 28mil  [TESTPOINT_050_028MIL]  138.48 39.62 270 top
TP223  Test point 28mil  [TESTPOINT_050_028MIL]  158.93 42.93 270 top
U1  TPD4S012DRYR  [UDFN6_1X1P5MM]  100.2 47.12 270 top
U2  AW-AM510  [MODULE_WIFI_0P9_12X12_44PIN]  8.64 33.91 90 top
U3  MP2182GTL-Z  [SOT583]  65.41 10.92 270 bottom
U4  MIMXRT106SDVL6A  [BGA196_0P65_10X10MM]  146.23 28.83 90 top
U5  W25Q128JWEIQ  [WSON8_1P27_8X6MM_EP183X205]  154.61 20.45 270 bottom
U6  PAM8013  [U-FLGA1515-9_SQ1P55MM]  97.28 4.57 0 bottom
U203  AP2127K-1.8TRG1  [SOT23-5]  158.42 11.56 0 top
U205  SN74AUP1T34  [SC70-5]  132 43.43 180 bottom
U207  SN74AUP1T34  [SC70-5]  162.1 11.3 270 top
U208  SN74AUP1T34  [SC70-5]  134.54 13.46 90 bottom
U209  MIC  [MIC6_3P6X2P75MM]  49.28 27.51 180 bottom
U210  MIC  [MIC6_3P6X2P75MM]  3.3 53.77 0 bottom
U211  MIC  [MIC6_3P6X2P75MM]  3.3 3.25 180 bottom
U212  SN74AUP1T34  [SC70-5]  50.55 35.18 270 top
U213  SN74AUP1T34  [SC70-5]  50.42 18.67 90 top
U214  74LVC1G157GV-Q100  [SC74_6P_1P7X3P1]  132 36.96 180 bottom
U215  APS6408L-OBM-BA  [PBGA24_1_6X8MM]  143.09 18.86 270 top
U216  APS1604M-SQR-SN  [SO8_1P27_4X5]  142.34 12.61 180 top
U217  74AVC4TD245BQ  [DHVQFN16_0P5_3P6X2P6]  59.94 31.37 180 bottom
U221  LSF0204PW-Q100  [TSSOP14]  65.02 24.51 0 bottom
Y1  32.768 kHz  [XTLOSC4_3P2X2P5MM_SM]  11.43 45.34 270 top
Y2  24MHZ  [XTLOSC4_3P2X2P5MM_SM]  154.19 33.54 315 top
Y3  32.768 KHZ  [XTAL2_1P7X1P1]  152.57 29.64 270 top

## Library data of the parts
BMP60-BMP64 = Bumper_RD_315w
C1-C3 C5-C7 C10 C16 C20 C21 C27-C32 C35 C36 C60-C63 C66-C68 C70 C114 C116 C122 C227-C231 C240-C253 C261 C262 C269-C276 C278 C279 = CAP_NP: room: EXT
C4 C11 C19 C22 C23 C25 C26 C37-C41 C123 C218 C221-C223 C225 C226 C232 C233 C236-C239 C254-C260 C277 = CAP_NP: room: MAIN
C24 C71 C73 C75 C76 C78 C81 C85-C87 C90 C92 C94 C96 C97 C101 C102 = CAP_NP: Tolerance: 20%; User Part Number: 150-77852; tolerance: 20%; room: MAIN
C69 C72 C80 C82 C83 C95 C100 C107 C112 = CAP_NP: Tolerance: 20%; User Part Number: 150-80019; tolerance: 20%; room: MAIN
C74 C84 C89 C98 C99 C106 C108 = CAP_NP: Tolerance: TOLERANCE; User Part Number: 150-80294; room: MAIN
C77 C79 = CAP_NP: Tolerance: 20%; User Part Number: 150-80329; tolerance: 20%; room: MAIN
C88 C91 C93 = CAP_NP: tolerance: 20%; room: MAIN
CON60 = USB_Type_C: room: EXT
D1 = DIODE_TVS_BIDIR: room: EXT
D2 = LED: room: MAIN
D60 = APTF1616LSEKJ_LED4: room: MAIN
FB1 L4 L61 = INDUCTOR: room: EXT
FB2 L3 = INDUCTOR: room: MAIN
FB3 FB4 = IND_FERRITE: room: EXT
J1 = CON1_COAX_SMA: room: EXT
J2 = CONN_PLUG_2X35: room: MAIN
J3 = CONN_HDR_2X35: room: EXT
J8 = CON_67_FEMALE_RA: room: EXT
J60 = HDR_SHRD_2X1: room: EXT
J61 J63 = CONN_HDR_3X1: room: MAIN
J62 = CONN_HDR_5X2: room: EXT
J64 = CONN_HDR_8X2: room: EXT
L1 = BEAD: room: EXT
L60 = DLW43: room: EXT
LS1 = SPEAKER_2P: room: EXT
M1 M2 = MIC_SPH0641LM4H-1_5P: room: MAIN
M3 M4 = MIC_SPH0641LM4H-1_5P: room: EXT
R1 R6 R8 R11-R18 R21-R24 R31 R32 R34-R42 R49 R53 R54 R62 R65 R70 R77 R78 R80-R82 R213-R217 R219 R221 R223-R227 R229 R244 R249 R259-R263 R280 R282 R283 R285-R288 R362 R366 R382-R386 = RES: room: MAIN
R2 R3 R5 R10 R19 R20 R25-R27 R29 R43-R48 R79 R218 R222 R228 R230-R236 R238 R240 R242 R243 R245 R247 R252 R254-R257 R289-R294 R300-R304 R306 R309 R312 R314-R319 R321-R349 R352 R357 R361 R363-R365 R367-R381 R387 = RES: room: EXT
R30 R33 = RES: tolerance: 5%; room: MAIN
R69 R71 = RES: tolerance: 1%; room: MAIN
R72-R76 R237 R239 R241 R295-R298 R307 R308 R310 R311 = RES: tolerance: 1%; room: EXT
R264-R279 R281 R284 = RES: signal model: RES_RC0402_25_DISCRETE_0.45_MM__0; room: MAIN
R313 = RES_3PIN: room: EXT
SW60-SW62 = SW_TACT-SPST-2_SM: room: MAIN
SW64 = SW3_SPDT: room: MAIN
TP1-TP10 TP22 TP60 TP203 = TESTLOOP: room: EXT
TP11 TP12 TP14-TP21 TP64-TP66 TP201 TP202 TP206 = TESTLOOP: room: MAIN
TP61 TP63 = T POINT S: room: EXT
TP208 TP209 = Test pad: room: EXT
TP210-TP218 TP220 TP221 TP223 = Test pad: room: MAIN
U1 = TPD4S012_6P: room: EXT
U2 = AW-AM510_44P: room: EXT
U3 = MP2182GTL_8P: room: EXT
U4 = MIMXRT106ADVL6A: room: MAIN
U5 = W25X80_8P_EP: room: MAIN
U6 = PAM8013: room: EXT
U203 = AP2127-FIXED_5P: room: MAIN
U205 U207 U208 = SN74AUP1T34_5P: room: MAIN
U209-U211 = MIC_SPH0645LM4H_6P: room: EXT
U212 U213 = SN74AUP1T34_5P: room: EXT
U214 = 74LVC1G157_6P: room: MAIN
U215 = APS6408L-OBMX_24P: room: MAIN
U216 = APS1604M_SOIC_8P: room: MAIN
U217 = 74AVC4TD245BQ_DHVQFN16: room: EXT
U221 = LSF0204_TSSOP14: room: EXT
Y1 = CLKGEN-SM_A: room: EXT
Y2 = XTAL_13: room: MAIN
Y3 = XTAL: room: MAIN

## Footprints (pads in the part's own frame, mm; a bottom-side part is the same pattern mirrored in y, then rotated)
6_22X6_38_SW
  rect 2.21x1.397 smd: 1(-4.445,1.994) 2(4.445,1.994) 3(-4.445,-1.994) 4(4.445,-1.994)
BGA196_0P65_10X10MM
  round 0.254 smd: A1(-4.225,4.225) A2(-3.575,4.225) A3(-2.925,4.225) A4(-2.275,4.225) A5(-1.625,4.225) A6(-0.975,4.225) A7(-0.325,4.225) A8(0.325,4.225) A9(0.975,4.225) A10(1.625,4.225) A11(2.275,4.225) A12(2.925,4.225) A13(3.575,4.225) A14(4.225,4.225) B1(-4.225,3.575) B2(-3.575,3.575) B3(-2.925,3.575) B4(-2.275,3.575) B5(-1.625,3.575) B6(-0.975,3.575) B7(-0.325,3.575) B8(0.325,3.575) B9(0.975,3.575) B10(1.625,3.575) B11(2.275,3.575) B12(2.925,3.575) B13(3.575,3.575) B14(4.225,3.575) C1(-4.225,2.925) C2(-3.575,2.925) C3(-2.925,2.925) C4(-2.275,2.925) C5(-1.625,2.925) C6(-0.975,2.925) C7(-0.325,2.925) C8(0.325,2.925) C9(0.975,2.925) C10(1.625,2.925) C11(2.275,2.925) C12(2.925,2.925) C13(3.575,2.925) C14(4.225,2.925) D1(-4.225,2.275) D2(-3.575,2.275) D3(-2.925,2.275) D4(-2.275,2.275) D5(-1.625,2.275) D6(-0.975,2.275) D7(-0.325,2.275) D8(0.325,2.275) D9(0.975,2.275) D10(1.625,2.275) D11(2.275,2.275) D12(2.925,2.275) D13(3.575,2.275) D14(4.225,2.275) E1(-4.225,1.625) E2(-3.575,1.625) E3(-2.925,1.625) E4(-2.275,1.625) E5(-1.625,1.625) E6(-0.975,1.625) E7(-0.325,1.625) E8(0.325,1.625) E9(0.975,1.625) E10(1.625,1.625) E11(2.275,1.625) E12(2.925,1.625) E13(3.575,1.625) E14(4.225,1.625) F1(-4.225,0.975) F2(-3.575,0.975) F3(-2.925,0.975) F4(-2.275,0.975) F5(-1.625,0.975) F6(-0.975,0.975) F7(-0.325,0.975) F8(0.325,0.975) F9(0.975,0.975) F10(1.625,0.975) F11(2.275,0.975) F12(2.925,0.975) F13(3.575,0.975) F14(4.225,0.975) G1(-4.225,0.325) G2(-3.575,0.325) G3(-2.925,0.325) G4(-2.275,0.325) G5(-1.625,0.325) G6(-0.975,0.325) G7(-0.325,0.325) G8(0.325,0.325) G9(0.975,0.325) G10(1.625,0.325) G11(2.275,0.325) G12(2.925,0.325) G13(3.575,0.325) G14(4.225,0.325) H1(-4.225,-0.325) H2(-3.575,-0.325) H3(-2.925,-0.325) H4(-2.275,-0.325) H5(-1.625,-0.325) H6(-0.975,-0.325) H7(-0.325,-0.325) H8(0.325,-0.325) H9(0.975,-0.325) H10(1.625,-0.325) H11(2.275,-0.325) H12(2.925,-0.325) H13(3.575,-0.325) H14(4.225,-0.325) J1(-4.225,-0.975) J2(-3.575,-0.975) J3(-2.925,-0.975) J4(-2.275,-0.975) J5(-1.625,-0.975) J6(-0.975,-0.975) J7(-0.325,-0.975) J8(0.325,-0.975) J9(0.975,-0.975) J10(1.625,-0.975) J11(2.275,-0.975) J12(2.925,-0.975) J13(3.575,-0.975) J14(4.225,-0.975) K1(-4.225,-1.625) K2(-3.575,-1.625) K3(-2.925,-1.625) K4(-2.275,-1.625) K5(-1.625,-1.625) K6(-0.975,-1.625) K7(-0.325,-1.625) K8(0.325,-1.625) K9(0.975,-1.625) K10(1.625,-1.625) K11(2.275,-1.625) K12(2.925,-1.625) K13(3.575,-1.625) K14(4.225,-1.625) L1(-4.225,-2.275) L2(-3.575,-2.275) L3(-2.925,-2.275) L4(-2.275,-2.275) L5(-1.625,-2.275) L6(-0.975,-2.275) L7(-0.325,-2.275) L8(0.325,-2.275) L9(0.975,-2.275) L10(1.625,-2.275) L11(2.275,-2.275) L12(2.925,-2.275) L13(3.575,-2.275) L14(4.225,-2.275) M1(-4.225,-2.925) M2(-3.575,-2.925) M3(-2.925,-2.925) M4(-2.275,-2.925) M5(-1.625,-2.925) M6(-0.975,-2.925) M7(-0.325,-2.925) M8(0.325,-2.925) M9(0.975,-2.925) M10(1.625,-2.925) M11(2.275,-2.925) M12(2.925,-2.925) M13(3.575,-2.925) M14(4.225,-2.925) N1(-4.225,-3.575) N2(-3.575,-3.575) N3(-2.925,-3.575) N4(-2.275,-3.575) N5(-1.625,-3.575) N6(-0.975,-3.575) N7(-0.325,-3.575) N8(0.325,-3.575) N9(0.975,-3.575) N10(1.625,-3.575) N11(2.275,-3.575) N12(2.925,-3.575) N13(3.575,-3.575) N14(4.225,-3.575) P1(-4.225,-4.225) P2(-3.575,-4.225) P3(-2.925,-4.225) P4(-2.275,-4.225) P5(-1.625,-4.225) P6(-0.975,-4.225) P7(-0.325,-4.225) P8(0.325,-4.225) P9(0.975,-4.225) P10(1.625,-4.225) P11(2.275,-4.225) P12(2.925,-4.225) P13(3.575,-4.225) P14(4.225,-4.225)
BUMPER_RD_315MIL
  round 0.127 smd: 1(0,0)
CC0201
  rect 0.47x0.381 smd: 1(-0.343,0) 2(0.343,0)
CC0402_25
  round 0.635 smd: 1(-0.508,0) 2(0.508,0)
CC0402_TOL0P2
  rect 0.457x0.61 smd: 1(-0.475,0) 2(0.475,0)
CC0402_TOL0P15
  rect 0.457x0.61 smd: 1(-0.475,0) 2(0.475,0)
CC0603_OV
  oval 0.889x1.143 smd: 1(-0.762,0) 2(0.762,0)
CC0805_OV
  oval 0.889x1.524 smd: 1(-0.965,0) 2(0.965,0)
CC1210
  rect 1.778x2.845 smd: 1(-1.397,0) 2(1.397,0)
CON4_COAX_RF_2P7SQ_SMT
  rect 0.991x0.991 smd: 1(0,-1.495) 3(0,1.495)
  rect 1.041x2.21 smd: 2(-1.471,0) 4(1.471,0)
CON24_USB_TYPEC_RA_9P64X8P55_SMT
  rect 0.305x0.711 smd: A1(-3,4.17) A2(-2.5,4.17) A3(-2,4.17) A4(-1.5,4.17) A5(-1,4.17) A6(-0.5,4.17) A7(0.5,4.17) A8(1,4.17) A9(1.5,4.17) A10(2,4.17) A11(2.5,4.17) A12(3,4.17) B2(2.25,2.47) B3(1.75,2.47) B4(1.25,2.47) B5(0.75,2.47) B6(0.25,2.47) B7(-0.25,2.47) B8(-0.75,2.47) B9(-1.25,2.47) B10(-1.75,2.47) B11(-2.25,2.47)
  rect 0.889x0.711 smd: B1(3.05,2.47) B12(-3.05,2.47)
  oval 1.092x2.108 hole 0.61x1.6: SH1(-4.32,3.36) SH2(4.32,3.36)
  oval 1.092x3.607 hole 0.61x2.108: SH3(4.62,-1.543) SH4(-4.62,-1.543)
CON70_SKT_0P635_SM
  rect 2.489x2.007 smd: (-14.5,0) (14.5,0)
  round 0 hole 0.889 unplated: (-12.45,0)
  round 0 hole 0.711 unplated: (12.45,0)
  rect 0.356x2.515 smd: 1(-10.795,-2.35) 2(-10.795,2.35) 3(-10.16,-2.35) 4(-10.16,2.35) 5(-9.525,-2.35) 6(-9.525,2.35) 7(-8.89,-2.35) 8(-8.89,2.35) 9(-8.255,-2.35) 10(-8.255,2.35) 11(-7.62,-2.35) 12(-7.62,2.35) 13(-6.985,-2.35) 14(-6.985,2.35) 15(-6.35,-2.35) 16(-6.35,2.35) 17(-5.715,-2.35) 18(-5.715,2.35) 19(-5.08,-2.35) 20(-5.08,2.35) 21(-4.445,-2.35) 22(-4.445,2.35) 23(-3.81,-2.35) 24(-3.81,2.35) 25(-3.175,-2.35) 26(-3.175,2.35) 27(-2.54,-2.35) 28(-2.54,2.35) 29(-1.905,-2.35) 30(-1.905,2.35) 31(-1.27,-2.35) 32(-1.27,2.35) 33(-0.635,-2.35) 34(-0.635,2.35) 35(0,-2.35) 36(0,2.35) 37(0.635,-2.35) 38(0.635,2.35) 39(1.27,-2.35) 40(1.27,2.35) 41(1.905,-2.35) 42(1.905,2.35) 43(2.54,-2.35) 44(2.54,2.35) 45(3.175,-2.35) 46(3.175,2.35) 47(3.81,-2.35) 48(3.81,2.35) 49(4.445,-2.35) 50(4.445,2.35) 51(5.08,-2.35) 52(5.08,2.35) 53(5.715,-2.35) 54(5.715,2.35) 55(6.35,-2.35) 56(6.35,2.35) 57(6.985,-2.35) 58(6.985,2.35) 59(7.62,-2.35) 60(7.62,2.35) 61(8.255,-2.35) 62(8.255,2.35) 63(8.89,-2.35) 64(8.89,2.35) 65(9.525,-2.35) 66(9.525,2.35) 67(10.16,-2.35) 68(10.16,2.35) 69(10.795,-2.35) 70(10.795,2.35)
CON70M_25_SM
  rect 2.489x2.007 smd: (-13.85,0) (13.85,0)
  round 0 hole 0.889 unplated: (-12.05,0)
  round 0 hole 0.711 unplated: (12.05,0)
  rect 0.356x1.803 smd: 1(-10.795,2.1) 2(-10.795,-2.1) 3(-10.16,2.1) 4(-10.16,-2.1) 5(-9.525,2.1) 6(-9.525,-2.1) 7(-8.89,2.1) 8(-8.89,-2.1) 9(-8.255,2.1) 10(-8.255,-2.1) 11(-7.62,2.1) 12(-7.62,-2.1) 13(-6.985,2.1) 14(-6.985,-2.1) 15(-6.35,2.1) 16(-6.35,-2.1) 17(-5.715,2.1) 18(-5.715,-2.1) 19(-5.08,2.1) 20(-5.08,-2.1) 21(-4.445,2.1) 22(-4.445,-2.1) 23(-3.81,2.1) 24(-3.81,-2.1) 25(-3.175,2.1) 26(-3.175,-2.1) 27(-2.54,2.1) 28(-2.54,-2.1) 29(-1.905,2.1) 30(-1.905,-2.1) 31(-1.27,2.1) 32(-1.27,-2.1) 33(-0.635,2.1) 34(-0.635,-2.1) 35(0,2.1) 36(0,-2.1) 37(0.635,2.1) 38(0.635,-2.1) 39(1.27,2.1) 40(1.27,-2.1) 41(1.905,2.1) 42(1.905,-2.1) 43(2.54,2.1) 44(2.54,-2.1) 45(3.175,2.1) 46(3.175,-2.1) 47(3.81,2.1) 48(3.81,-2.1) 49(4.445,2.1) 50(4.445,-2.1) 51(5.08,2.1) 52(5.08,-2.1) 53(5.715,2.1) 54(5.715,-2.1) 55(6.35,2.1) 56(6.35,-2.1) 57(6.985,2.1) 58(6.985,-2.1) 59(7.62,2.1) 60(7.62,-2.1) 61(8.255,2.1) 62(8.255,-2.1) 63(8.89,2.1) 64(8.89,-2.1) 65(9.525,2.1) 66(9.525,-2.1) 67(10.16,2.1) 68(10.16,-2.1) 69(10.795,2.1) 70(10.795,-2.1)
CON_67_0P5_22X7P75_RA
  rect 1.194x2.743 smd: (-10.35,3.125) (10.35,3.125)
  round 0 hole 1.092 unplated: (-10,-1.375)
  round 0 hole 1.6 unplated: (10,-1.375)
  rect 0.305x1.549 smd: 1(-9.25,3.9) 2(-9,-3.65) 3(-8.75,3.9) 4(-8.5,-3.65) 5(-8.25,3.9) 6(-8,-3.65) 7(-7.75,3.9) 8(-7.5,-3.65) 9(-7.25,3.9) 10(-7,-3.65) 11(-6.75,3.9) 12(-6.5,-3.65) 13(-6.25,3.9) 14(-6,-3.65) 15(-5.75,3.9) 16(-5.5,-3.65) 17(-5.25,3.9) 18(-5,-3.65) 19(-4.75,3.9) 20(-4.5,-3.65) 21(-4.25,3.9) 22(-4,-3.65) 23(-3.75,3.9) 32(-1.5,-3.65) 33(-1.25,3.9) 34(-1,-3.65) 35(-0.75,3.9) 36(-0.5,-3.65) 37(-0.25,3.9) 38(0,-3.65) 39(0.25,3.9) 40(0.5,-3.65) 41(0.75,3.9) 42(1,-3.65) 43(1.25,3.9) 44(1.5,-3.65) 45(1.75,3.9) 46(2,-3.65) 47(2.25,3.9) 48(2.5,-3.65) 49(2.75,3.9) 50(3,-3.65) 51(3.25,3.9) 52(3.5,-3.65) 53(3.75,3.9) 54(4,-3.65) 55(4.25,3.9) 56(4.5,-3.65) 57(4.75,3.9) 58(5,-3.65) 59(5.25,3.9) 60(5.5,-3.65) 61(5.75,3.9) 62(6,-3.65) 63(6.25,3.9) 64(6.5,-3.65) 65(6.75,3.9) 66(7,-3.65) 67(7.25,3.9) 68(7.5,-3.65) 69(7.75,3.9) 70(8,-3.65) 71(8.25,3.9) 72(8.5,-3.65) 73(8.75,3.9) 74(9,-3.65) 75(9.25,3.9)
DHVQFN16_0P5_3P6X2P6
  rect 0.305x0.838 smd: 1(-0.25,1.719) 8(-0.25,-1.719) 9(0.25,-1.719) 16(0.25,1.719)
  rect 0.838x0.305 smd: 2(-1.219,1.25) 3(-1.219,0.75) 4(-1.219,0.25) 5(-1.219,-0.25) 6(-1.219,-0.75) 7(-1.219,-1.25) 10(1.219,-1.25) 11(1.219,-0.75) 12(1.219,-0.25) 13(1.219,0.25) 14(1.219,0.75) 15(1.219,1.25)
  rect 1.143x2.159 smd: 17(0,0)
DIODE_0402
  rect 0.584x0.559 smd: 1(-0.483,0) 2(0.483,0)
HDR102
  rect 1.524x1.524 hole 1.016: 1(0,0)
  round 1.524 hole 1.016: 2(0,-2.54)
HDR103_STAG_SM
  rect 3.175x1.27 smd: 1(-1.575,-2.54) 2(1.575,0) 3(-1.575,2.54)
HDR205_10M_50_SM_K
  rect 0.737x2.794 smd: 1(-2.54,-2.032) 2(-2.54,2.032) 3(-1.27,-2.032) 4(-1.27,2.032) 5(0,-2.032) 6(0,2.032) 7(1.27,-2.032) 8(1.27,2.032) 9(2.54,-2.032) 10(2.54,2.032)
HDR208_TSM_SM
  rect 3.175x1.27 smd: 1(-2.67,8.89) 2(2.67,8.89) 3(-2.67,6.35) 4(2.67,6.35) 5(-2.67,3.81) 6(2.67,3.81) 7(-2.67,1.27) 8(2.67,1.27) 9(-2.67,-1.27) 10(2.67,-1.27) 11(-2.67,-3.81) 12(2.67,-3.81) 13(-2.67,-6.35) 14(2.67,-6.35) 15(-2.67,-8.89) 16(2.67,-8.89)
IND4_CHOKE_0603
  rect 0.584x0.305 smd: 1(-0.66,-0.279) 2(0.66,-0.279) 3(0.66,0.279) 4(-0.66,0.279)
IND_2P7X2P2MM
  rect 1.092x2.007 smd: 1(-0.95,0) 2(0.95,0)
IND_0603
  rect 0.991x0.813 smd: 1(-0.69,0) 2(0.69,0)
IND_0603A
  rect 1.016x1.016 smd: 1(-0.69,0) 2(0.69,0)
IND_1608
  rect 0.61x0.813 smd: 1(-0.7,0) 2(0.7,0)
LED4_1P75_1P8SQ_SMT
  rect 0.838x0.508 smd: 1(-0.875,0.5) 2(0.875,0.5) 3(0.875,-0.5) 4(-0.875,-0.5)
LED_0603
  rect 0.838x0.787 smd: A(-0.775,0) C(0.775,0)
MIC5_3P6X2P75MM
  round 0 hole 0.381 unplated: (0,-0.71)
  rect 0.711x0.508 smd: 1(-0.831,1.364) 2(-0.831,0.542) 4(0.831,0.542) 5(0.831,1.364)
  custom 0.405x0.405 smd: 3(-0.66,-0.71)
MIC6_3P6X2P75MM
  round 0 hole 0.381 unplated: (0,-0.71)
  rect 0.711x0.508 smd: 1(-0.9,1.364) 2(-0.9,0.542) 4(0.9,0.542) 5(0.9,1.364) 6(0,1.364)
  custom 0.405x0.405 smd: 3(-0.66,-0.71)
MODULE_WIFI_0P9_12X12_44PIN
  rect 0.991x0.508 smd: 1(-5.595,4.5) 2(-5.595,3.6) 3(-5.595,2.7) 4(-5.595,1.8) 5(-5.595,0.9) 6(-5.595,0) 7(-5.595,-0.9) 8(-5.595,-1.8) 9(-5.595,-2.7) 10(-5.595,-3.6) 11(-5.595,-4.5) 23(5.595,-4.5) 24(5.595,-3.6) 25(5.595,-2.7) 26(5.595,-1.8) 27(5.595,-0.9) 28(5.595,0) 29(5.595,0.9) 30(5.595,1.8) 31(5.595,2.7) 32(5.595,3.6) 33(5.595,4.5)
  rect 0.508x0.991 smd: 12(-4.5,-5.595) 13(-3.6,-5.595) 14(-2.7,-5.595) 15(-1.8,-5.595) 16(-0.9,-5.595) 17(0,-5.595) 18(0.9,-5.595) 19(1.8,-5.595) 20(2.7,-5.595) 21(3.6,-5.595) 22(4.5,-5.595) 34(4.5,5.595) 35(3.6,5.595) 36(2.7,5.595) 37(1.8,5.595) 38(0.9,5.595) 39(0,5.595) 40(-0.9,5.595) 41(-1.8,5.595) 42(-2.7,5.595) 43(-3.6,5.595) 44(-4.5,5.595)
PBGA24_1_6X8MM
  round 0.33 smd: A2(-1,2) A3(0,2) A4(1,2) A5(2,2) B1(-2,1) B2(-1,1) B3(0,1) B4(1,1) B5(2,1) C1(-2,0) C2(-1,0) C3(0,0) C4(1,0) C5(2,0) D1(-2,-1) D2(-1,-1) D3(0,-1) D4(1,-1) D5(2,-1) E1(-2,-2) E2(-1,-2) E3(0,-2) E4(1,-2) E5(2,-2)
RC0201
  rect 0.47x0.381 smd: 1(-0.343,0) 2(0.343,0)
RC0402_25
  round 0.635 smd: 1(-0.508,0) 2(0.508,0)
RC0402_X2
  round 0.635 smd: 1(-0.508,0) 2(0.508,0) 3(1.524,0)
RC0603_OV
  oval 0.889x1.143 smd: 1(-0.762,0) 2(0.762,0)
RC0805_OV
  oval 0.889x1.524 smd: 1(-0.965,0) 2(0.965,0)
SC70-5
  rect 0.406x0.813 smd: 1(-0.65,-1.079) 2(0,-1.079) 3(0.65,-1.079) 4(0.65,1.079) 5(-0.65,1.079)
SC74_6P_1P7X3P1
  rect 0.991x0.711 smd: 1(-1.2,0.95) 2(-1.2,0) 3(-1.2,-0.95) 4(1.2,-0.95) 5(1.2,0) 6(1.2,0.95)
SO8_1P27_4X5
  rect 1.6x0.61 smd: 1(-2.7,1.905) 2(-2.7,0.635) 3(-2.7,-0.635) 4(-2.7,-1.905) 5(2.7,-1.905) 6(2.7,-0.635) 7(2.7,0.635) 8(2.7,1.905)
SOT23-5
  rect 0.61x1.118 smd: 1(-0.95,-1.425) 2(0,-1.425) 3(0.95,-1.425) 4(0.95,1.425) 5(-0.95,1.425)
SOT583
  rect 0.61x0.254 smd: 1(-0.7,0.75) 2(-0.7,0.25) 3(-0.7,-0.25) 4(-0.7,-0.75) 5(0.7,-0.75) 6(0.7,-0.25) 7(0.7,0.25) 8(0.7,0.75)
SPEAKER_31X28_TH
  round 0 hole 3.658 unplated: (0,0) (0,-36.8)
SW3_SPDT_SM
  rect 0.787x0.991 smd: (-3.75,1.15) (-3.75,-1.15) (3.75,1.15) (3.75,-1.15)
  round 0 hole 0.889 unplated: (-1.5,0) (1.5,0)
  rect 0.711x1.092 smd: 1(2.25,-2.05) 2(-0.75,-2.05) 3(-2.25,-2.05)
TESTPOINT_050_028MIL
  round 1.27 hole 0.711: 1(0,0)
TP_040_100MIL_TH
  round 2.54 hole 1.016: 1(0,0)
TPAD_020
  round 0.508 smd: 1(0,0)
TSSOP14
  rect 1.524x0.457 smd: 1(-2.959,1.951) 2(-2.959,1.3) 3(-2.959,0.65) 4(-2.959,0) 5(-2.959,-0.65) 6(-2.959,-1.3) 7(-2.959,-1.951) 8(2.959,-1.951) 9(2.959,-1.3) 10(2.959,-0.65) 11(2.959,0) 12(2.959,0.65) 13(2.959,1.3) 14(2.959,1.951)
U-FLGA1515-9_SQ1P55MM
  rect 0.533x0.533 smd: A1(-0.587,0.587) A3(0.587,0.587) C1(-0.587,-0.587) C3(0.587,-0.587)
  rect 0.279x0.533 smd: A2(0,0.587) C2(0,-0.587)
  rect 0.533x0.279 smd: B1(-0.587,0) B3(0.587,0)
  rect 0.279x0.279 smd: B2(0,0)
UDFN6_1X1P5MM
  rect 0.584x0.305 smd: 1(-0.418,0.5)
  rect 0.508x0.305 smd: 2(-0.38,0) 3(-0.38,-0.5) 4(0.38,-0.5) 5(0.38,0) 6(0.38,0.5)
unnamed#2
  round 1.524 smd: (0,0)
unnamed#3
  round 0 hole 0.635 unplated: (-0.254,2.54) (-0.254,1.27)
  round 0 hole 1.016 unplated: (0,3.81) (0,0)
unnamed#4
  round 6.502 hole 4.191: 1(0,0)
WSON8_1P27_8X6MM_EP183X205
  rect 0.914x0.508 smd: 1(-3.901,1.905) 2(-3.901,0.635) 3(-3.901,-0.635) 4(-3.901,-1.905) 5(3.901,-1.905) 6(3.901,-0.635) 7(3.901,0.635) 8(3.901,1.905)
  rect 4.648x5.207 smd: 9(0,0)
XTAL2_1P7X1P1
  rect 0.508x1.016 smd: 1(-0.55,0) 2(0.55,0)
XTLOSC4_3P2X2P5MM_SM
  rect 1.397x1.194 smd: 1(-1.1,-0.8) 2(1.1,-0.8) 3(1.1,0.8) 4(-1.1,0.8)

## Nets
GND: C2.2 C3.2 C4.2 C5.2 C6.2 C7.2 C10.2 C11.2 C16.2 C19.2 C20.2 C21.2 C22.2 C23.2 C24.2 C25.2 C26.2 C27.2 C28.2 C31.2 C32.2 C35.2 C36.2 C37.2 C38.2 C39.2 C40.2 C41.2 C60.2 C61.2 C62.2 C63.2 C66.2 C67.2 C68.2 C69.2 C70.2 C71.2 C72.2 C73.2 C74.2 C75.2 C76.2 C77.2 C78.2 C79.2 C80.2 C81.2 C82.2 C83.2 C84.2 C85.2 C86.2 C87.2 C88.2 C89.2 C90.2 C91.2 C92.2 C93.2 C94.2 C95.2 C96.2 C97.2 C98.2 C99.2 C100.2 C101.2 C102.2 C106.2 C107.2 C108.2 C112.2 C114.2 C116.2 C122.2 C123.2 C218.2 C221.2 C222.2 C223.2 C225.2 C226.2 C227.2 C228.2 C229.2 C230.2 C231.2 C232.2 C233.2 C236.2 C237.2 C238.2 C239.2 C240.2 C241.2 C242.2 C243.2 C244.2 C245.2 C246.2 C247.2 C248.2 C249.2 C250.2 C251.2 C252.2 C253.2 C254.2 C255.2 C256.2 C257.2 C258.2 C259.2 C260.2 C261.2 C262.2 C269.2 C270.2 C271.2 C272.2 C273.2 C274.2 C275.2 C276.2 C277.2 C278.2 C279.2 CON60.A1 CON60.A12 CON60.B1 CON60.B12 D1.1 D60.1 FB1.1 J1.2 J1.3 J1.4(GND3) J2.2 J2.3 J2.6 J2.11 J2.12 J2.15 J2.16 J2.20 J2.21 J2.25 J2.34 J2.43 J2.46 J2.49 J2.54 J2.57 J2.58 J2.61 J2.62 J2.68 J3.2 J3.3 J3.6 J3.11 J3.12 J3.15 J3.16 J3.20 J3.21 J3.25 J3.34 J3.43 J3.46 J3.49 J3.54 J3.57 J3.58 J3.61 J3.62 J3.68 J8.1 J8.7 J8.18 J8.33 J8.39 J8.45 J8.51 J8.57 J8.63 J8.69 J8.75 J62.3 J62.5 J64.15 J64.16(B8) M1.3 M2.3 M3.3 M4.3 R3.2 R5.2 R8.2 R11.2 R18.1 R21.1 R24.1 R31.1 R33.2 R34.1 R35.1 R36.1 R37.1 R38.1 R39.1 R42.1 R45.2 R46.2 R65.1 R77.1 R78.1 R79.2 R236.2 R238.2 R240.2 R242.2 R247.2 R249.2 R252.2 R259.2 R261.2 R263.2 R284.2 R285.2 R315.2 R317.2 R323.2 R337.2 R340.2 R361.2 R366.2 R373.2 R375.2 SW60.3 SW60.4 SW61.3 SW61.4 SW62.3 SW62.4 SW64.3(NO) TP15.1(PIN1) TP64.1(PIN1) TP65.1(PIN1) TP210.1(PIN1) TP213.1(PIN1) TP221.1(PIN1) U1.4 U2.1 U2.3 U2.20 U2.31 U2.33 U2.36 U3.4 U4.A1 U4.A14 U4.B5 U4.B10 U4.E2 U4.E13 U4.G7 U4.G8 U4.H7 U4.H8 U4.J7 U4.J8 U4.K2 U4.K6 U4.K9 U4.K13 U4.L9 U4.N1 U4.N2 U4.N5 U4.N8 U4.P1 U4.P14 U5.4 U5.9 U6.A2 U6.B3 U203.2 U205.3 U207.3 U208.3 U209.3 U210.3 U211.3 U212.3 U213.3 U214.1 U214.2 U215.B3 U215.C1 U215.E5(VSSQ_2) U216.4(VSS) U217.8 U217.17 U221.7 Y1.2 Y2.2 Y2.4
VBUS_5V: C114.1 C116.1 C122.1 C271.1 C272.1 C273.1 J2.50 J3.50 R6.2 R313.1 U3.2(VIN) U6.B1(VDD) U6.B2
VBUS_5VDD: FB2.1 J2.67 J2.69 J3.67 J3.69 J60.2 R6.1 R387.2 TP220.1(PIN1)
VBUS_5VDD_E: C5.1 C10.1 CON60.A4 CON60.A9 CON60.B4 CON60.B9(VBUS_B9) J60.1 U1.6(VBUS)
VDD_1V8: C25.1 C26.1 C38.1 C39.1 C40.1 C41.1 C107.1 C108.1 C232.1 C237.1 C239.1 C240.1 C241.1 C242.1 C243.1 C244.1 C245.1 C246.1 C247.1 C248.1 C249.1 C251.1 C253.1 C270.1 J2.40 J2.42 J3.40 J3.42 M1.2 M1.5(VDD) M2.2 M2.5(VDD) M3.2 M3.5(VDD) M4.2 M4.5(VDD) R14.1 R17.1 R30.1 R213.2 R214.2 R217.2 R237.1 R239.1 R241.1 R287.2 R294.1 R303.2 R321.2 R377.2 R379.2 R381.2 R383.2 TP223.1(PIN1) U4.K5(NVCC_SD1) U5.8 U205.5(VCCB) U207.1 U208.1 U209.5 U210.5 U211.5 U212.1 U213.5(VCCB) U221.1
VDD_OPI: C255.1 C256.1 C257.1 C258.1 R280.1 R282.1 R286.2 R287.1 R288.1 U215.B4 U215.D1 U215.E4
VDD_QSPI: C259.1 C260.1 R283.1 R382.2 R383.1 U216.8
VDD_SOC_IN: C24.1 C90.1 C91.1 C92.1 C93.1 C94.1 C95.1 C96.1 C101.1 L3.2 TP21.1(PIN1) U4.F6 U4.F7 U4.F8 U4.F9 U4.G6 U4.G9 U4.H6 U4.H9 U4.J5 U4.J9
VDD_USB_3V: C84.1 C88.1 U4.K8
ANT_50E: C1.1 C3.1 U2.2
AUDIO_SD: J2.10 U4.E8
AUDIO_SD_EXT: J3.10 R79.1 U6.C2
B: D60.4 R81.2
BT_DEV_WAKE: TP2.1(PIN1) U2.6
BT_DEV_WAKE_LS: J8.42
BT_HOST_WAKE: J2.18 U4.B14
BT_HOST_WAKE_EXT: J3.18 R301.1 TP3.1(PIN1)
BT_HOST_WAKE_LS: R295.2 R300.2 R352.2 U221.2
BT_REG_ON: J2.22 U4.C14
BT_REG_ON_EXT: J3.22 R319.1 R339.1 TP10.1(PIN1)
BT_REG_ON_LS: R310.2 R338.1 U221.5
BT_UART1_CTS: J2.29 U4.H14
BT_UART1_CTS_EXT: J3.29 R292.2 TP9.1(PIN1)
BT_UART1_CTS_LS: R345.2 R348.2 R370.1
BT_UART1_RTS: J2.53 U4.L10
BT_UART1_RTS_EXT: J3.53 R371.2 TP6.1(PIN1)
BT_UART1_RTS_LS: R289.1 R342.2 R349.2
BT_UART1_RXD: J2.44 TP212.1(PIN1) U4.L14
BT_UART1_RXD_EXT: J3.44 R291.2 TP8.1(PIN1)
BT_UART1_RXD_LS: R344.2 R346.2 R369.1
BT_UART1_TXD: J2.35 TP211.1(PIN1) U4.K14
BT_UART1_TXD_EXT: J3.35 R372.2 TP7.1(PIN1)
BT_UART1_TXD_LS: R290.1 R343.2 R347.2
CC1: CON60.A5 R5.1
CC2: CON60.B5 R3.1
